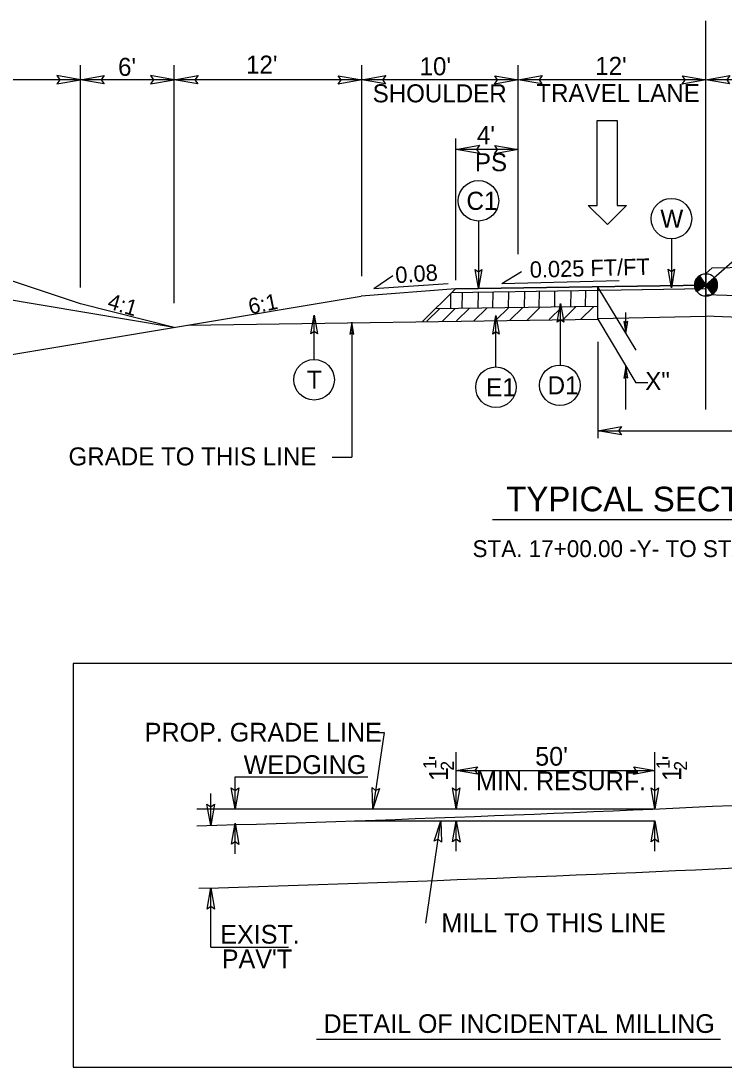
# Model space of a CAD drawing. Extents: x 2176024 to 2177225, y 75947 to 76635.
# Drawn here: x 2176984.7 to 2177029.6, y 76461.3 to 76528.3 of the extents above; entities that cross this region are included whole.
import ezdxf

# ---------------------------------------------------------------- set-up
doc = ezdxf.new("R2010")
doc.units = 0
for name, color, linetype in [('Exist XS Ground Line', 7, 'Continuous'), ('Old_Level_1', 7, 'Continuous'), ('Old_Level_11', 7, 'Continuous'), ('Old_Level_21', 7, 'Continuous'), ('Old_Level_3', 7, 'Continuous'), ('Old_Level_4', 7, 'Continuous'), ('Prop Dimension', 7, 'Continuous'), ('Prop Pavement Schedule Description CELL', 7, 'Continuous'), ('Prop Terminator CELL', 7, 'Continuous'), ('Typical Curb CELL', 7, 'Continuous'), ('Typical Grade Point Symbol CELL', 7, 'Continuous'), ('Typical Pavement Slope CELL', 7, 'Continuous'), ('Typical Pavement Slope Information CELL', 7, 'Continuous'), ('Typical Shoulder Slope CELL', 7, 'Continuous'), ('Typical Slope Point Local CELL', 7, 'Continuous'), ('Typical Terminator CELL', 7, 'Continuous'), ('Typical Text General CELL', 7, 'Continuous'), ('Typical Text Label CELL', 7, 'Continuous')]:
    doc.layers.add(name, color=color, linetype=linetype)

msp = doc.modelspace()

# ---------------------------------------------------------------- linework, layer by layer
at = {"layer": 'Exist XS Ground Line'}
for p in [(2177021.542, 76509.216), (2177051.603, 76508.521)]:
    msp.add_line(p, (2177028.462, 76509.359), dxfattribs=at)
at = {"layer": 'Old_Level_1'}
for p, q in [((2177012.88, 76509.866), (2177012.894, 76510.882)), ((2177013.898, 76509.879), (2177013.912, 76510.893)), ((2177014.838, 76509.887), (2177014.853, 76510.912)), ((2177015.835, 76509.911), (2177015.85, 76510.922)), ((2177016.855, 76509.932), (2177016.87, 76510.946)), ((2177017.795, 76509.939), (2177017.81, 76510.965)), ((2177018.793, 76509.963), (2177018.807, 76510.975)), ((2177019.826, 76509.976), (2177019.84, 76510.99)), ((2177020.766, 76509.983), (2177020.781, 76511.009)), ((2177012.136, 76509.853), (2177012.15, 76510.827)), ((2177010.616, 76509.044), (2177011.431, 76509.843)), ((2177011.606, 76509.044), (2177012.432, 76509.854)), ((2177012.499, 76509.063), (2177013.334, 76509.881)), ((2177013.618, 76509.067), (2177014.454, 76509.885)), ((2177015.026, 76509.107), (2177015.862, 76509.926)), ((2177015.912, 76509.113), (2177016.748, 76509.932)), ((2177017.032, 76509.117), (2177017.867, 76509.936)), ((2177018.44, 76509.158), (2177019.275, 76509.976)), ((2177019.324, 76509.162), (2177020.16, 76509.98)), ((2177020.443, 76509.165), (2177021.284, 76509.989)), ((2177014.801, 76496.354), (2177042.123, 76496.354))]:
    msp.add_line(p, q, dxfattribs=at)
at = {"layer": 'Old_Level_11'}
for p, q in [((2177013.914, 76515.455), (2177013.914, 76511.152)), ((2177032.62, 76515.001), (2177028.462, 76511.362)), ((2177026.251, 76514.312), (2177026.251, 76511.179)), ((2177019.162, 76506.241), (2177019.162, 76510.186)), ((2177003.402, 76506.597), (2177003.402, 76509.439)), ((2177015.033, 76506.118), (2177015.033, 76509.414))]:
    msp.add_line(p, q, dxfattribs=at)
for points in [[(2177014.121, 76512.352), (2177013.914, 76511.152), (2177013.701, 76512.359), (2177013.914, 76512.206)], [(2177026.458, 76512.379), (2177026.251, 76511.179), (2177026.038, 76512.385), (2177026.251, 76512.232)], [(2177018.956, 76508.986), (2177019.162, 76510.186), (2177019.376, 76508.979), (2177019.162, 76509.132)], [(2177003.196, 76508.239), (2177003.402, 76509.439), (2177003.616, 76508.233), (2177003.402, 76508.386)], [(2177014.826, 76508.214), (2177015.033, 76509.414), (2177015.246, 76508.208), (2177015.033, 76508.361)]]:
    msp.add_lwpolyline(points, close=True, dxfattribs=at)
for centre in [(2177013.914, 76516.751), (2177026.251, 76515.608), (2177003.402, 76505.301), (2177019.116, 76504.946), (2177015.033, 76504.822)]:
    msp.add_circle(centre, 1.296, dxfattribs=at)
at = {"layer": 'Old_Level_21'}
msp.add_line((2177003.558, 76463.108), (2177029.395, 76463.108), dxfattribs=at)
at = {"layer": 'Old_Level_4'}
for p, q in [((2177021.509, 76516.459), (2177021.509, 76521.891)), ((2177021.509, 76521.891), (2177022.789, 76521.891)), ((2177022.789, 76521.891), (2177022.789, 76516.459)), ((2177022.168, 76515.237), (2177020.927, 76516.459)), ((2177020.927, 76516.459), (2177021.509, 76516.459)), ((2177023.371, 76516.459), (2177022.168, 76515.237)), ((2177022.789, 76516.459), (2177023.371, 76516.459))]:
    msp.add_line(p, q, dxfattribs=at)
at = {"layer": 'Prop Dimension'}
for p, q in [((2177028.462, 76525.231), (2177028.462, 76528.26)), ((2176988.462, 76511.212), (2176988.462, 76525.42)), ((2176994.462, 76510.194), (2176994.462, 76525.42)), ((2177006.462, 76511.922), (2177006.462, 76525.42)), ((2177016.462, 76513.339), (2177016.462, 76525.42)), ((2177028.462, 76503.401), (2177028.462, 76525.231)), ((2176988.462, 76524.493), (2176978.462, 76524.493)), ((2176994.462, 76524.493), (2176988.462, 76524.493)), ((2177006.462, 76524.493), (2176994.462, 76524.493)), ((2177016.462, 76524.493), (2177006.462, 76524.493)), ((2177028.462, 76524.493), (2177016.568, 76524.493)), ((2177043.462, 76524.493), (2177028.568, 76524.493)), ((2177012.462, 76511.667), (2177012.462, 76520.742)), ((2177016.462, 76520.032), (2177012.462, 76520.032)), ((2177021.542, 76511.202), (2177023.967, 76507.194)), ((2177023.33, 76508.27), (2177023.33, 76509.598)), ((2177005.817, 76508.978), (2177005.817, 76500.343)), ((2177021.542, 76509.187), (2177023.968, 76505.093)), ((2177021.54, 76507.735), (2177021.54, 76501.572)), ((2177023.331, 76503.392), (2177023.331, 76506.168)), ((2177024.748, 76505.093), (2177023.968, 76505.093)), ((2177021.54, 76502.04), (2177051.603, 76502.04)), ((2177004.556, 76500.343), (2177005.817, 76500.343)), ((2177012.494, 76477.84), (2177012.494, 76481.479)), ((2177025.189, 76477.84), (2177025.189, 76481.479)), ((2176998.349, 76477.84), (2176998.349, 76479.884)), ((2176996.795, 76476.786), (2176996.795, 76478.83)), ((2176998.349, 76474.973), (2176998.349, 76476.926)), ((2177005.976, 76477.081), (2177025.189, 76477.081)), ((2177012.494, 76475.128), (2177012.494, 76477.081)), ((2177025.189, 76475.128), (2177025.189, 76477.081)), ((2176996.795, 76468.997), (2176996.795, 76472.781))]:
    msp.add_line(p, q, dxfattribs=at)
for radius in [1926.833, 1930.833]:
    msp.add_arc((2176939.502, 78402.766), radius, 271.677655, 272.884773, dxfattribs=at)
at = {"layer": 'Prop Pavement Schedule Description CELL'}
msp.add_lwpolyline([(2176987.99, 76461.322), (2177043.916, 76461.322), (2177043.916, 76487.15), (2176987.99, 76487.15)], close=True, dxfattribs=at)
at = {"layer": 'Prop Terminator CELL'}
for points in [[(2177013.844, 76480.06), (2177012.494, 76480.292), (2177013.851, 76480.532), (2177013.679, 76480.292)], [(2177023.839, 76480.525), (2177025.189, 76480.292), (2177023.832, 76480.052), (2177024.004, 76480.292)], [(2176998.582, 76479.19), (2176998.349, 76477.84), (2176998.109, 76479.197), (2176998.349, 76479.025)], [(2177007.578, 76479.141), (2177007.151, 76477.84), (2177007.112, 76479.218), (2177007.324, 76479.012)], [(2177012.726, 76479.19), (2177012.494, 76477.84), (2177012.254, 76479.197), (2177012.494, 76479.025)], [(2177025.422, 76479.19), (2177025.189, 76477.84), (2177024.949, 76479.197), (2177025.189, 76479.025)], [(2176997.027, 76478.136), (2176996.795, 76476.786), (2176996.555, 76478.143), (2176996.795, 76477.971)], [(2176998.117, 76475.576), (2176998.349, 76476.926), (2176998.589, 76475.568), (2176998.349, 76475.741)], [(2177011.079, 76475.779), (2177011.506, 76477.081), (2177011.545, 76475.703), (2177011.333, 76475.908)], [(2177012.261, 76475.731), (2177012.494, 76477.081), (2177012.734, 76475.723), (2177012.494, 76475.896)], [(2177024.957, 76475.731), (2177025.189, 76477.081), (2177025.429, 76475.723), (2177025.189, 76475.896)], [(2176996.562, 76471.431), (2176996.795, 76472.781), (2176997.035, 76471.423), (2176996.795, 76471.596)]]:
    msp.add_lwpolyline(points, close=True, dxfattribs=at)
at = {"layer": 'Typical Curb CELL'}
for p, q in [((2177021.542, 76509.187), (2177021.542, 76511.259)), ((2176995.346, 76508.797), (2177021.542, 76509.187))]:
    msp.add_line(p, q, dxfattribs=at)
at = {"layer": 'Typical Grade Point Symbol CELL'}
for p, q in [((2177028.05, 76511.954), (2177028.462, 76511.362)), ((2177028.462, 76511.362), (2177029.054, 76511.774)), ((2177027.869, 76510.952), (2177028.462, 76511.362)), ((2177028.462, 76511.362), (2177027.869, 76510.952)), ((2177028.874, 76510.77), (2177028.462, 76511.362))]:
    msp.add_line(p, q, dxfattribs=at)
for points in [[(2177028.217, 76511.714), (2177027.741, 76511.383)], [(2177028.225, 76511.703), (2177027.741, 76511.366)], [(2177028.209, 76511.726), (2177027.742, 76511.401)], [(2177028.233, 76511.691), (2177027.742, 76511.349)], [(2177028.241, 76511.679), (2177027.742, 76511.331)], [(2177028.25, 76511.667), (2177027.742, 76511.314)], [(2177028.2, 76511.738), (2177027.743, 76511.42)], [(2177028.258, 76511.655), (2177027.744, 76511.297)], [(2177028.192, 76511.75), (2177027.745, 76511.439)], [(2177028.266, 76511.643), (2177027.746, 76511.281)], [(2177028.184, 76511.762), (2177027.747, 76511.458)], [(2177028.274, 76511.632), (2177027.747, 76511.265)], [(2177028.176, 76511.774), (2177027.75, 76511.477)], [(2177028.283, 76511.62), (2177027.75, 76511.249)], [(2177028.167, 76511.785), (2177027.753, 76511.497)], [(2177028.291, 76511.608), (2177027.753, 76511.234)], [(2177028.299, 76511.596), (2177027.756, 76511.218)], [(2177028.159, 76511.797), (2177027.758, 76511.518)], [(2177028.307, 76511.584), (2177027.759, 76511.203)], [(2177028.316, 76511.572), (2177027.762, 76511.187)], [(2177028.151, 76511.809), (2177027.763, 76511.539)], [(2177028.324, 76511.561), (2177027.766, 76511.173)], [(2177028.143, 76511.821), (2177027.769, 76511.561)], [(2177028.332, 76511.549), (2177027.771, 76511.158)], [(2177028.34, 76511.537), (2177027.775, 76511.143)], [(2177028.134, 76511.833), (2177027.776, 76511.583)], [(2177028.126, 76511.845), (2177027.783, 76511.606)], [(2177028.118, 76511.856), (2177027.792, 76511.629)], [(2177028.11, 76511.868), (2177027.802, 76511.654)], [(2177028.101, 76511.88), (2177027.815, 76511.681)], [(2177028.093, 76511.892), (2177027.829, 76511.708)], [(2177028.085, 76511.904), (2177027.846, 76511.737)], [(2177028.077, 76511.916), (2177027.865, 76511.768)], [(2177028.069, 76511.927), (2177027.892, 76511.805)], [(2177028.06, 76511.939), (2177027.926, 76511.846)], [(2177028.052, 76511.951), (2177027.988, 76511.906)], [(2177029.057, 76511.768), (2177029.057, 76511.768), (2177028.466, 76511.357)], [(2177029.066, 76511.757), (2177028.474, 76511.345)], [(2177029.073, 76511.744), (2177028.482, 76511.333)], [(2177029.081, 76511.732), (2177028.49, 76511.321)], [(2177029.088, 76511.719), (2177028.499, 76511.309)], [(2177029.095, 76511.707), (2177028.507, 76511.298)], [(2177029.102, 76511.694), (2177028.515, 76511.286)], [(2177029.108, 76511.681), (2177028.523, 76511.274)], [(2177029.115, 76511.668), (2177028.532, 76511.262)], [(2177029.121, 76511.655), (2177028.54, 76511.25)], [(2177029.127, 76511.641), (2177028.548, 76511.238)], [(2177029.132, 76511.627), (2177028.556, 76511.227)], [(2177029.138, 76511.614), (2177028.565, 76511.215)], [(2177029.142, 76511.599), (2177028.573, 76511.203)], [(2177029.148, 76511.585), (2177028.581, 76511.191)], [(2177029.152, 76511.571), (2177028.589, 76511.179)], [(2177029.156, 76511.556), (2177028.597, 76511.167)], [(2177029.161, 76511.542), (2177028.606, 76511.156)], [(2177028.349, 76511.525), (2177027.781, 76511.13)], [(2177028.357, 76511.513), (2177027.785, 76511.115)], [(2177028.365, 76511.501), (2177027.79, 76511.102)], [(2177028.373, 76511.49), (2177027.796, 76511.088)], [(2177028.382, 76511.478), (2177027.802, 76511.074)], [(2177028.39, 76511.466), (2177027.807, 76511.061)], [(2177028.398, 76511.454), (2177027.814, 76511.048)], [(2177028.406, 76511.442), (2177027.82, 76511.034)], [(2177028.414, 76511.43), (2177027.827, 76511.021)], [(2177028.423, 76511.419), (2177027.834, 76511.009)], [(2177028.431, 76511.407), (2177027.841, 76510.996)], [(2177028.439, 76511.395), (2177027.849, 76510.984)], [(2177028.447, 76511.383), (2177027.856, 76510.971)], [(2177028.456, 76511.371), (2177027.864, 76510.959), (2177027.864, 76510.959)], [(2177029.164, 76511.526), (2177028.614, 76511.144)], [(2177029.167, 76511.511), (2177028.622, 76511.132)], [(2177029.169, 76511.495), (2177028.63, 76511.12)], [(2177029.172, 76511.48), (2177028.639, 76511.108)], [(2177029.175, 76511.464), (2177028.647, 76511.096)], [(2177029.177, 76511.448), (2177028.655, 76511.085)], [(2177029.179, 76511.431), (2177028.663, 76511.073)], [(2177029.18, 76511.415), (2177028.672, 76511.061)], [(2177029.182, 76511.399), (2177028.68, 76511.049)], [(2177029.182, 76511.381), (2177028.688, 76511.037)], [(2177029.183, 76511.364), (2177028.696, 76511.025)], [(2177029.182, 76511.346), (2177028.704, 76511.014)], [(2177029.182, 76511.328), (2177028.713, 76511.002)], [(2177029.181, 76511.31), (2177028.721, 76510.99)], [(2177029.179, 76511.291), (2177028.729, 76510.978)], [(2177029.177, 76511.272), (2177028.737, 76510.966)], [(2177029.174, 76511.253), (2177028.746, 76510.954)], [(2177029.171, 76511.233), (2177028.754, 76510.943)], [(2177029.167, 76511.213), (2177028.762, 76510.931)], [(2177029.162, 76511.192), (2177028.77, 76510.919)], [(2177029.156, 76511.17), (2177028.779, 76510.907)], [(2177029.15, 76511.148), (2177028.787, 76510.895)], [(2177029.142, 76511.125), (2177028.795, 76510.883)], [(2177029.133, 76511.101), (2177028.803, 76510.872)], [(2177029.123, 76511.077), (2177028.812, 76510.86)], [(2177029.112, 76511.051), (2177028.82, 76510.848)], [(2177029.099, 76511.025), (2177028.828, 76510.836)], [(2177029.082, 76510.995), (2177028.836, 76510.824)], [(2177029.063, 76510.964), (2177028.844, 76510.812)], [(2177029.038, 76510.93), (2177028.853, 76510.801)], [(2177029.006, 76510.889), (2177028.861, 76510.789)], [(2177028.953, 76510.835), (2177028.869, 76510.777)]]:
    msp.add_lwpolyline(points, dxfattribs=at)
msp.add_circle((2177028.462, 76511.363), 0.721, dxfattribs=at)
for start, end in [(124.8249, 214.8249), (304.8249, 34.8249)]:
    msp.add_arc((2177028.462, 76511.363), 0.721, start, end, dxfattribs=at)
at = {"layer": 'Typical Pavement Slope CELL'}
for p, q in [((2177028.462, 76512.091), (2177028.857, 76512.455)), ((2177028.857, 76512.455), (2177035.967, 76512.639)), ((2177028.462, 76512.091), (2177028.462, 76510.755)), ((2176994.462, 76508.65), (2176978.462, 76511.316)), ((2177012.449, 76511.124), (2177010.333, 76509.02)), ((2176978.462, 76505.983), (2177006.414, 76510.642)), ((2177028.462, 76510.755), (2177043.463, 76510.287)), ((2177021.53, 76509.993), (2177011.156, 76509.838)), ((2176995.913, 76477.84), (2177025.189, 76477.84))]:
    msp.add_line(p, q, dxfattribs=at)
at = {"layer": 'Typical Pavement Slope Information CELL'}
for p, q in [((2177015.412, 76511.455), (2177016.669, 76512.225)), ((2177007.221, 76511.145), (2177008.446, 76511.964)), ((2177015.412, 76511.455), (2177022.917, 76511.651)), ((2177007.221, 76511.145), (2177011.967, 76511.459))]:
    msp.add_line(p, q, dxfattribs=at)
at = {"layer": 'Typical Shoulder Slope CELL'}
for p, q in [((2176988.462, 76510.15), (2176978.462, 76513.483)), ((2177012.449, 76511.124), (2177006.414, 76510.642)), ((2176994.462, 76508.65), (2176988.462, 76510.15))]:
    msp.add_line(p, q, dxfattribs=at)
at = {"layer": 'Typical Slope Point Local CELL'}
for p, q in [((2177028.475, 76511.112), (2177012.194, 76510.87)), ((2177028.462, 76511.362), (2177012.449, 76511.124))]:
    msp.add_line(p, q, dxfattribs=at)
msp.add_lwpolyline([(2177012.449, 76511.124), (2177028.462, 76511.362), (2177028.462, 76511.362), (2177028.462, 76511.112), (2177028.462, 76511.112), (2177012.194, 76510.87)], close=True, dxfattribs=at)
at = {"layer": 'Typical Terminator CELL'}
for points in [[(2176986.952, 76524.233), (2176988.462, 76524.493), (2176986.944, 76524.761), (2176987.137, 76524.493)], [(2176989.972, 76524.233), (2176988.462, 76524.493), (2176989.98, 76524.761), (2176989.787, 76524.493)], [(2176992.952, 76524.233), (2176994.462, 76524.493), (2176992.944, 76524.761), (2176993.137, 76524.493)], [(2176995.972, 76524.233), (2176994.462, 76524.493), (2176995.98, 76524.761), (2176995.787, 76524.493)], [(2177004.952, 76524.752), (2177006.462, 76524.493), (2177004.944, 76524.224), (2177005.137, 76524.493)], [(2177007.972, 76524.233), (2177006.462, 76524.493), (2177007.98, 76524.761), (2177007.787, 76524.493)], [(2177014.952, 76524.752), (2177016.462, 76524.493), (2177014.944, 76524.224), (2177015.137, 76524.493)], [(2177017.972, 76524.233), (2177016.462, 76524.493), (2177017.98, 76524.761), (2177017.787, 76524.493)], [(2177026.952, 76524.752), (2177028.462, 76524.493), (2177026.944, 76524.224), (2177027.137, 76524.493)], [(2177029.972, 76524.233), (2177028.462, 76524.493), (2177029.98, 76524.761), (2177029.787, 76524.493)], [(2177013.972, 76519.772), (2177012.462, 76520.032), (2177013.98, 76520.301), (2177013.787, 76520.032)], [(2177014.952, 76520.292), (2177016.462, 76520.032), (2177014.944, 76519.764), (2177015.137, 76520.032)], [(2177005.947, 76508.223), (2177005.817, 76508.978), (2177005.682, 76508.219), (2177005.817, 76508.316)], [(2177023.198, 76509.024), (2177023.33, 76508.27), (2177023.462, 76509.029), (2177023.328, 76508.932)], [(2177023.463, 76505.413), (2177023.331, 76506.168), (2177023.199, 76505.409), (2177023.333, 76505.505)], [(2177023.049, 76501.78), (2177021.54, 76502.04), (2177023.058, 76502.308), (2177022.865, 76502.04)]]:
    msp.add_lwpolyline(points, close=True, dxfattribs=at)
at = {"layer": 'Typical Text General CELL'}
for p, q in [((2177007.007, 76482.728), (2177007.873, 76482.728)), ((2177007.873, 76482.728), (2177007.151, 76477.84)), ((2177012.494, 76480.292), (2177025.189, 76480.292)), ((2176998.349, 76479.884), (2177006.83, 76479.884)), ((2177010.539, 76470.53), (2177011.506, 76477.081)), ((2176996.795, 76468.997), (2177001.766, 76468.997))]:
    msp.add_line(p, q, dxfattribs=at)

# ---------------------------------------------------------------- texts
at = {"layer": 'Old_Level_11'}
for s, rotation, p in [('C1', 0.00026, (2177013.145, 76516.171)), ('W', 0.00026, (2177025.544, 76515.028)), ('T', 359.99974, (2177002.945, 76504.721)), ('D1', 0.00026, (2177018.331, 76504.366)), ('E1', 0.00026, (2177014.405, 76504.242))]:
    msp.add_text(s, height=1.16, rotation=rotation, dxfattribs=at).set_placement(p)
msp.add_text('X"', height=1.1533, dxfattribs=at).set_placement((2177024.577, 76504.643))
at = {"layer": 'Old_Level_21'}
msp.add_text('DETAIL OF INCIDENTAL MILLING', height=1.19356, dxfattribs=at).set_placement((2177004.014, 76463.508))
at = {"layer": 'Old_Level_3'}
msp.add_text('TYPICAL SECTION NO.  2', height=1.5766, rotation=0.00002, dxfattribs=at).set_placement((2177015.688, 76496.882))
at = {"layer": 'Typical Pavement Slope Information CELL'}
for s, height, rotation, p in [('0.025 FT/FT', 1.04295, 1.49319, (2177017.206, 76511.824)), ('0.08', 1.0429, 3.78012, (2177008.631, 76511.475))]:
    msp.add_text(s, height=height, rotation=rotation, dxfattribs=at).set_placement(p)
at = {"layer": 'Typical Slope Point Local CELL'}
for s, rotation, p in [('4:1', 343.53506, (2176990.129, 76509.883)), ('6:1', 11.48655, (2176999.314, 76509.479))]:
    msp.add_text(s, height=1.0064, rotation=rotation, dxfattribs=at).set_placement(p)
at = {"layer": 'Typical Text General CELL'}
for s, height, p in [("6'", 1.1533, (2176990.868, 76524.745)), ("12' ", 1.1533, (2176999.053, 76524.888)), ("10' ", 1.1533, (2177010.15, 76524.781)), ("12'", 1.1533, (2177021.38, 76524.808)), ('SHOULDER', 1.1533, (2177007.148, 76523.051)), ('TRAVEL LANE', 1.15334, (2177017.611, 76523.078)), ("4' ", 1.1533, (2177013.814, 76520.374)), ('PS', 1.1533, (2177013.685, 76518.644)), ('GRADE TO THIS LINE', 1.15334, (2176987.7, 76499.819))]:
    msp.add_text(s, height=height, dxfattribs=at).set_placement(p)
for s, height, rotation, p in [('PROP. GRADE LINE', 1.2, 360, (2176992.574, 76482.149)), ("50'", 1.2, 360, (2177017.542, 76480.609)), ('WEDGING', 1.2, 360, (2176998.901, 76480.074)), ('1', 0.84, 90, (2177011.221, 76480.387)), ("'", 1.2, 90, (2177011.961, 76480.951)), ('2', 0.84, 90, (2177012.341, 76480.286)), ('1', 0.84, 90, (2177026.135, 76480.387)), ("'", 1.2, 90, (2177026.875, 76480.951)), ('2', 0.84, 90, (2177027.255, 76480.286)), ('1', 1.2, 90, (2177011.961, 76479.625)), ('MIN. RESURF.', 1.2, 360, (2177013.757, 76479.036)), ('1', 1.2, 90, (2177026.875, 76479.625)), ('MILL TO THIS LINE', 1.2, 360, (2177011.543, 76469.954)), ('EXIST.', 1.2, 360, (2176997.403, 76469.221)), ("PAV'T", 1.2, 360, (2176997.501, 76467.647))]:
    msp.add_text(s, height=height, rotation=rotation, dxfattribs=at).set_placement(p)
at = {"layer": 'Typical Text Label CELL'}
msp.add_text('STA. 17+00.00 -Y- TO STA. 23+52.54 -Y-', height=1.0742, dxfattribs=at).set_placement((2177013.535, 76493.955))

doc.saveas('drawing.dxf')
